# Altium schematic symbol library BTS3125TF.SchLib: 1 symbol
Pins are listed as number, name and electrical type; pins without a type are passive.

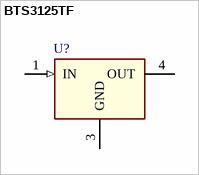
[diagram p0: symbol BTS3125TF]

## BTS3125TF
designator U?  (value not drawn)
HITFET Smart Low-Side Power Switch, VIN 5.5V, IL 2A; Manufacturer: Infineon Technologies
footprint TO228P998X250-3N-V1
footprint TO228P998X250-3N-1
pins: 1 IN (in) "Input Pin", 3 GND (power) "Ground,Source For Power DMOS", 4 OUT (power) "Drain,Load Connection For Power DMOS"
